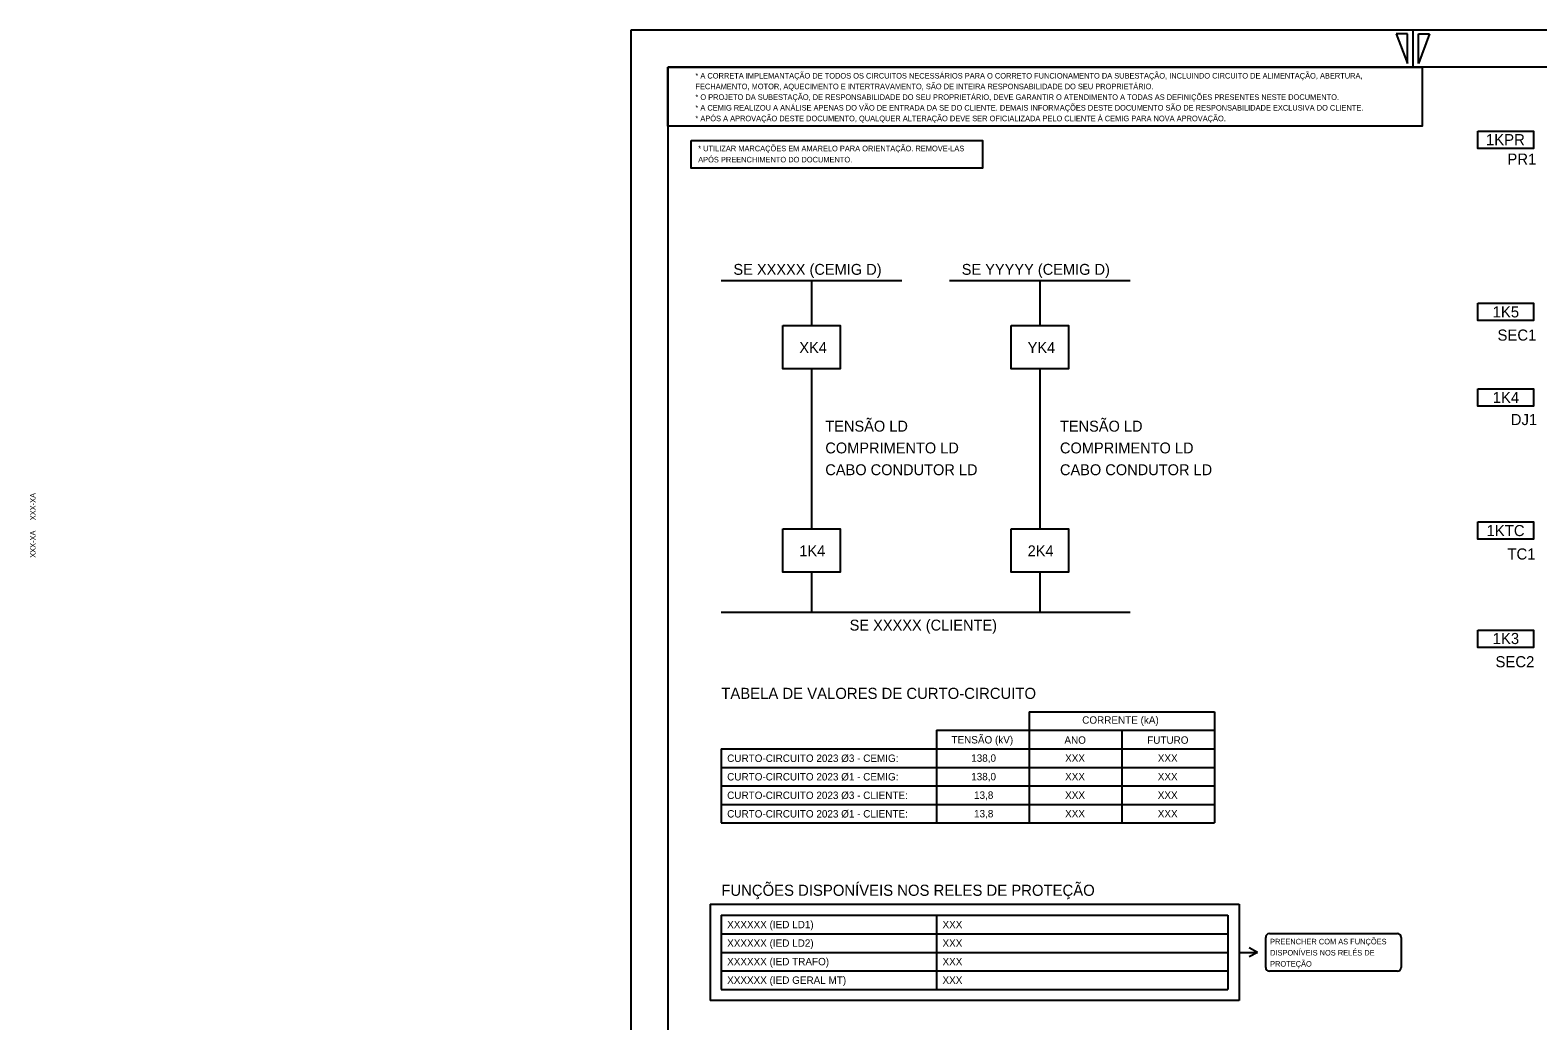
# Model space of a CAD drawing. Extents: x 400 to 1404, y 358 to 952.
# Drawn here: x 400.5 to 807.3, y 684.6 to 952 of the extents above; entities that cross this region are included whole.
import ezdxf

# ---------------------------------------------------------------- set-up
doc = ezdxf.new("R2010")
doc.units = 0
doc.layers.add('New Level (0)', color=7, linetype='Continuous')

# ---------------------------------------------------------------- blocks, each defined once
blk = doc.blocks.new('POINT_DISPLAY')
blk.add_line((0, 0), (0, 0))

msp = doc.modelspace()

# ---------------------------------------------------------------- linework, layer by layer
for p, q in [((586.96, 884.4), (635.66, 884.4)), ((611.31, 884.4), (611.31, 872.28)), ((648.56, 884.4), (697.25, 884.4)), ((672.91, 884.4), (672.91, 872.28)), ((611.31, 860.54), (611.31, 817.4)), ((672.91, 860.54), (672.91, 817.4)), ((611.31, 805.67), (611.31, 794.9)), ((672.91, 805.67), (672.91, 794.9)), ((586.96, 794.9), (697.25, 794.9))]:
    msp.add_line(p, q)
for points in [[(603.54, 872.28), (619.08, 872.28), (619.08, 860.54), (603.54, 860.54)], [(665.14, 872.28), (680.68, 872.28), (680.68, 860.54), (665.14, 860.54)], [(603.54, 817.4), (619.08, 817.4), (619.08, 805.67), (603.54, 805.67)], [(665.14, 817.4), (680.68, 817.4), (680.68, 805.67), (665.14, 805.67)]]:
    msp.add_lwpolyline(points, close=True)
at = {"layer": 'New Level (0)'}
for p, q in [((562.58, 951.96), (562.58, 357.96)), ((1403.58, 951.96), (562.58, 951.96)), ((1403.58, 951.96), (562.58, 951.96)), ((562.58, 951.96), (562.58, 357.96)), ((773.58, 951.96), (773.58, 941.96)), ((772.08, 950.96), (769.08, 950.96)), ((769.08, 950.96), (772.08, 942.96)), ((772.08, 942.96), (772.08, 950.96)), ((775.08, 942.96), (775.08, 950.96)), ((775.08, 950.96), (778.08, 950.96)), ((778.08, 950.96), (775.08, 942.96)), ((572.58, 941.96), (572.58, 367.96)), ((1393.58, 941.96), (572.58, 941.96)), ((572.58, 941.96), (572.58, 367.96)), ((670.01, 768.04), (670.01, 738.04)), ((670.01, 768.04), (720.01, 768.04)), ((720.01, 768.04), (720.01, 738.04)), ((645.01, 763.04), (645.01, 738.04)), ((645.01, 763.04), (720.01, 763.04)), ((695.01, 763.04), (695.01, 738.04)), ((586.96, 758.04), (720.01, 758.04)), ((586.96, 758.04), (586.96, 738.04)), ((586.96, 753.04), (720.01, 753.04)), ((586.96, 748.04), (720.01, 748.04)), ((586.96, 743.04), (720.01, 743.04)), ((586.96, 738.04), (720.01, 738.04)), ((583.96, 716.12), (726.65, 716.12)), ((583.96, 716.12), (583.96, 690.12)), ((726.65, 716.12), (726.65, 690.12)), ((586.96, 713.12), (723.65, 713.12)), ((586.96, 713.12), (586.96, 693.12)), ((586.96, 713.12), (723.65, 713.12)), ((645.01, 713.12), (645.01, 693.12)), ((723.65, 713.12), (723.65, 693.12)), ((586.96, 708.12), (723.65, 708.12)), ((734.84, 708.17), (742.19, 708.17)), ((742.19, 708.17), (769.38, 708.17)), ((731.68, 703.12), (729.38, 704.33)), ((733.84, 699.06), (733.84, 707.17)), ((770.38, 707.17), (770.38, 699.06)), ((586.96, 703.12), (723.65, 703.12)), ((726.65, 703.12), (731.68, 703.12)), ((731.68, 703.12), (729.38, 701.91)), ((586.96, 698.12), (723.65, 698.12)), ((769.38, 698.06), (734.84, 698.06)), ((586.96, 693.12), (723.65, 693.12)), ((726.65, 690.12), (583.96, 690.12))]:
    msp.add_line(p, q, dxfattribs=at)
for points in [[(572.58, 941.96), (776.08, 941.96), (776.08, 926.09), (572.58, 926.09)], [(791.1, 924.73), (806.12, 924.73), (806.12, 920.04), (791.1, 920.04)], [(578.87, 922.15), (657.43, 922.15), (657.43, 914.73), (578.87, 914.73)], [(791.1, 878.26), (806.12, 878.26), (806.12, 873.58), (791.1, 873.58)], [(791.1, 855.16), (806.12, 855.16), (806.12, 850.47), (791.1, 850.47)], [(791.1, 819.25), (806.12, 819.25), (806.12, 814.57), (791.1, 814.57)], [(791.1, 790.09), (806.12, 790.09), (806.12, 785.41), (791.1, 785.41)]]:
    msp.add_lwpolyline(points, close=True, dxfattribs=at)
for centre, start, end in [((734.84, 707.17), 90, 180), ((769.38, 707.17), 0, 90), ((734.84, 699.06), 180, 270), ((769.38, 699.06), 270, 0)]:
    msp.add_arc(centre, 1, start, end, dxfattribs=at)

# ---------------------------------------------------------------- block references
for p in [(670.01, 758.04), (670.01, 713.12)]:
    msp.add_blockref('POINT_DISPLAY', p, dxfattribs=at)

# ---------------------------------------------------------------- texts
for s, height, p in [('1KPR', 3, (793.28, 920.91)), ('* UTILIZAR MARCAÇÕES EM AMARELO PARA ORIENTAÇÃO. REMOVE-LAS ', 1.5, (580.73, 919.27)), ('APÓS PREENCHIMENTO DO DOCUMENTO.', 1.5, (580.73, 916.27)), ('PR1', 3, (799.06, 915.66)), ('SE XXXXX (CEMIG D)', 2.94, (590.23, 885.94)), ('SE YYYYY (CEMIG D)', 2.94, (651.83, 885.94)), ('1K5', 3, (795.08, 874.44)), ('SEC1', 3, (796.39, 868.18)), ('XK4', 2.94, (608.02, 864.85)), ('YK4', 2.94, (669.62, 864.85)), ('1K4', 3, (795.1, 851.34)), ('TENSÃO LD ', 2.94, (615.03, 843.63)), ('TENSÃO LD ', 2.94, (678.34, 843.63)), ('DJ1', 3, (799.97, 845.39)), ('COMPRIMENTO LD', 2.94, (615.03, 837.75)), ('COMPRIMENTO LD', 2.94, (678.34, 837.75)), ('CABO CONDUTOR LD ', 2.94, (615.03, 831.87)), ('CABO CONDUTOR LD ', 2.94, (678.34, 831.87)), ('1KTC', 3, (793.45, 815.43)), ('1K4', 2.94, (608.02, 809.98)), ('2K4', 2.94, (669.62, 809.98)), ('TC1', 3, (799.07, 809.11)), ('SE XXXXX (CLIENTE)', 2.94, (621.59, 789.95)), ('1K3', 3, (795.09, 786.3)), ('SEC2', 3, (795.85, 780.04)), ('TABELA DE VALORES DE CURTO-CIRCUITO', 3, (586.96, 771.5)), ('CORRENTE (kA)', 2, (684.34, 764.81)), ('TENSÃO (kV)', 2, (649.07, 759.48)), ('ANO', 2, (679.54, 759.4)), ('FUTURO', 2, (701.87, 759.4)), ('CURTO-CIRCUITO 2023 Ø3 - CEMIG:', 2, (588.55, 754.5)), ('138,0', 2, (654.39, 754.54)), ('XXX', 2, (679.73, 754.54)), ('XXX', 2, (704.73, 754.54)), ('CURTO-CIRCUITO 2023 Ø1 - CEMIG:', 2, (588.55, 749.5)), ('138,0', 2, (654.39, 749.54)), ('XXX', 2, (679.73, 749.54)), ('XXX', 2, (704.73, 749.54)), ('CURTO-CIRCUITO 2023 Ø3 - CLIENTE:', 2, (588.55, 744.5)), ('13,8', 2, (655.16, 744.54)), ('XXX', 2, (679.73, 744.54)), ('XXX', 2, (704.73, 744.54)), ('CURTO-CIRCUITO 2023 Ø1 - CLIENTE:', 2, (588.55, 739.5)), ('13,8', 2, (655.16, 739.54)), ('XXX', 2, (679.73, 739.54)), ('XXX', 2, (704.73, 739.54)), ('FUNÇÕES DISPONÍVEIS NOS RELES DE PROTEÇÃO', 3, (586.96, 718.37)), ('XXXXXX (IED LD1)', 2, (588.55, 709.62)), ('XXX', 2, (646.65, 709.62)), ('XXXXXX (IED LD2)', 2, (588.55, 704.62)), ('XXX', 2, (646.65, 704.62)), ('PREENCHER COM AS FUNÇÕES ', 1.5, (735.03, 705.27)), ('DISPONÍVEIS NOS RELÉS DE ', 1.5, (735.03, 702.27)), ('XXXXXX (IED TRAFO)', 2, (588.55, 699.62)), ('XXX', 2, (646.65, 699.62)), ('PROTEÇÃO', 1.5, (735.03, 699.27)), ('XXXXXX (IED GERAL MT)', 2, (588.55, 694.62)), ('XXX', 2, (646.65, 694.62))]:
    msp.add_text(s, height=height).set_placement(p)
for p in [(401.99, 819.72), (401.99, 809.58)]:
    msp.add_text('XXX-XA', height=1.5, rotation=90).set_placement(p)
for s, p in [('* A CORRETA IMPLEMANTAÇÃO DE TODOS OS CIRCUITOS NECESSÁRIOS PARA O CORRETO FUNCIONAMENTO DA SUBESTAÇÃO, INCLUINDO CIRCUITO DE ALIMENTAÇÃO, ABERTURA,   ', (579.98, 938.9)), ('FECHAMENTO, MOTOR, AQUECIMENTO E INTERTRAVAMENTO, SÃO DE INTEIRA RESPONSABILIDADE DO SEU PROPRIETÁRIO.', (579.98, 936.02)), ('* O PROJETO DA SUBESTAÇÃO, DE RESPONSABILIDADE DO SEU PROPRIETÁRIO, DEVE GARANTIR O ATENDIMENTO A TODAS AS DEFINIÇÕES PRESENTES NESTE DOCUMENTO.', (579.98, 933.14)), ('* A CEMIG REALIZOU A ANÁLISE APENAS DO VÃO DE ENTRADA DA SE DO CLIENTE. DEMAIS INFORMAÇÕES DESTE DOCUMENTO SÃO DE RESPONSABILIDADE EXCLUSIVA DO CLIENTE.', (579.98, 930.26)), ('* APÓS A APROVAÇÃO DESTE DOCUMENTO, QUALQUER ALTERAÇÃO DEVE SER OFICIALIZADA PELO CLIENTE À CEMIG PARA NOVA APROVAÇÃO.', (579.98, 927.38))]:
    msp.add_text(s, height=1.5, dxfattribs=at).set_placement(p)

doc.saveas('drawing.dxf')
